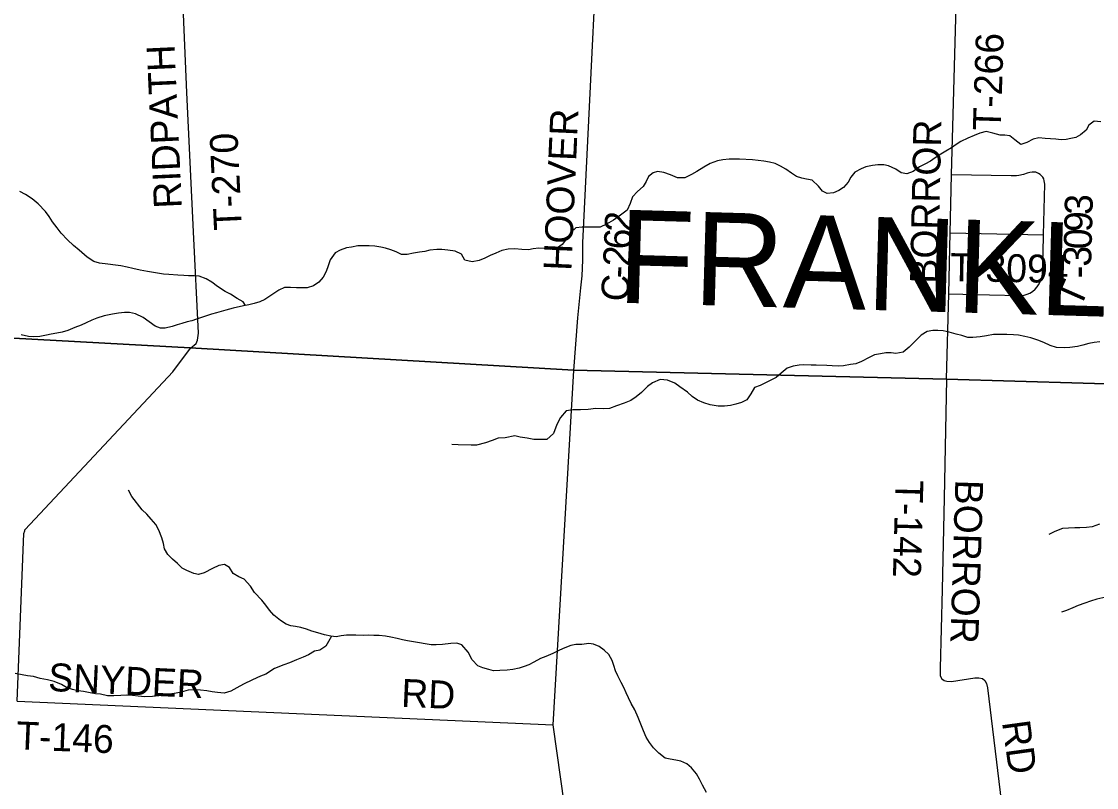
# Model space of a CAD drawing. Extents: x 114843 to 284848, y 317643 to 566895.
# Drawn here: x 179255 to 190810, y 325529 to 333758 of the extents above; entities that cross this region are included whole.
import ezdxf

# ---------------------------------------------------------------- set-up
doc = ezdxf.new("R2010")
doc.units = 0
for name, color, linetype in [('GM_X_County', 7, 'Continuous'), ('GM_X_County_Road', 7, 'Continuous'), ('GM_X_County_Road_Text', 7, 'Continuous'), ('GM_X_County_Text', 7, 'Continuous'), ('GM_X_Minor_River', 7, 'Continuous'), ('GM_X_Township', 7, 'Continuous'), ('GM_X_Township_Road', 7, 'Continuous'), ('GM_X_Township_Road_Text', 7, 'Continuous')]:
    doc.layers.add(name, color=color, linetype=linetype)

msp = doc.modelspace()

# ---------------------------------------------------------------- linework, layer by layer
at = {"layer": 'GM_X_County'}
for points in [[(234342, 327551), (226718, 328004), (223790, 328228), (218560, 328476), (218545, 328480), (213225, 328765), (208151, 329070), (208095, 329072), (206187, 329142), (202770, 329336), (202310, 329362), (198524, 329604), (197724, 329650), (193708, 329789), (193408, 329799), (192869, 329809), (189197, 329917), (185190, 330012), (181070, 330253), (177726, 330436)], [(177726, 330436), (181070, 330253), (185190, 330012), (189197, 329917), (192869, 329809), (193408, 329799), (193708, 329789), (197724, 329650), (198524, 329604), (202310, 329362), (202770, 329336), (206187, 329142), (208095, 329072), (208151, 329070), (213225, 328765), (218545, 328480), (218560, 328476), (223790, 328228), (226718, 328004), (234342, 327551)]]:
    msp.add_lwpolyline(points, dxfattribs=at)
at = {"layer": 'GM_X_County_Road'}
for points in [[(185191, 330009), (185235, 330573), (185269, 330895), (185281, 331026), (185287, 331193), (185289, 331381), (185389, 333425), (185415, 333935), (185439, 334426), (185464, 334887), (185471, 335221), (185475, 335891), (185479, 336859), (185483, 337354)], [(185504, 322567), (185296, 323893), (184971, 326203), (185191, 330009)]]:
    msp.add_lwpolyline(points, dxfattribs=at)
at = {"layer": 'GM_X_Minor_River'}
for points in [[(190858, 332681), (190786, 332687), (190729, 332643), (190697, 332591), (190639, 332541), (190587, 332513), (190533, 332501), (190483, 332491), (190431, 332487), (190371, 332493), (190315, 332496), (190259, 332502), (190191, 332508), (190129, 332494), (190061, 332458), (189997, 332436), (189933, 332486), (189877, 332528), (189825, 332536), (189773, 332538), (189697, 332557), (189625, 332575), (189557, 332559), (189496, 332533), (189428, 332505), (189352, 332467), (189300, 332435), (189250, 332401), (189190, 332365), (189136, 332331)], [(189136, 332331), (189076, 332295), (189026, 332257), (188964, 332227), (188906, 332195), (188841, 332147), (188773, 332121), (188711, 332131), (188653, 332173), (188575, 332209), (188523, 332217), (188459, 332217), (188401, 332212), (188331, 332196), (188279, 332176), (188213, 332138), (188171, 332086), (188139, 332031), (188091, 331973), (188040, 331943), (187984, 331919), (187916, 331911), (187864, 331936), (187822, 331988), (187752, 332052), (187694, 332064), (187642, 332074), (187586, 332094), (187530, 332127), (187470, 332171), (187412, 332205), (187356, 332231), (187294, 332247), (187234, 332259), (187172, 332265), (187112, 332271), (186972, 332280), (186922, 332280), (186860, 332280), (186794, 332272), (186736, 332262), (186658, 332234), (186588, 332192), (186514, 332148), (186456, 332116), (186384, 332080), (186305, 332078), (186230, 332110), (186161, 332136), (186093, 332145), (186043, 332131), (185993, 332093), (185969, 332040), (185937, 331986), (185875, 331932), (185823, 331876), (185799, 331804), (185767, 331732), (185692, 331678), (185620, 331624), (185544, 331580), (185474, 331550), (185416, 331548), (185354, 331548), (185280, 331550), (185214, 331540), (185164, 331494), (185124, 331438), (185067, 331364), (185005, 331320), (184937, 331308), (184873, 331320), (184815, 331324), (184755, 331316), (184705, 331304), (184633, 331309), (184557, 331315), (184485, 331311), (184419, 331297), (184353, 331269), (184293, 331243), (184235, 331217), (184173, 331191), (184099, 331177), (184020, 331195), (183985, 331259), (183915, 331290), (183839, 331300), (183773, 331310), (183720, 331310), (183644, 331300), (183592, 331288), (183534, 331280), (183468, 331270), (183400, 331256), (183340, 331256), (183282, 331282), (183226, 331304), (183168, 331323), (183116, 331333), (183054, 331343)], [(181663, 330708), (181638, 330745), (181572, 330783), (181500, 330830), (181444, 330858), (181362, 330910), (181302, 330956), (181240, 330994), (181166, 331021), (181112, 331027), (181050, 331027), (181000, 331029), (180936, 331033), (180838, 331041), (180780, 331043), (180696, 331057), (180608, 331073), (180532, 331088), (180452, 331106), (180392, 331120), (180322, 331134), (180266, 331140), (180182, 331150), (180092, 331162), (180032, 331178), (179962, 331227), (179874, 331303), (179814, 331353), (179748, 331413), (179680, 331484), (179638, 331542), (179590, 331606), (179552, 331664), (179512, 331718), (179436, 331799), (179370, 331853), (179300, 331901), (179236, 331933)], [(183054, 331343), (182992, 331349), (182926, 331349), (182872, 331347), (182802, 331335), (182748, 331325), (182682, 331303), (182626, 331271), (182573, 331197), (182553, 331133), (182529, 331071), (182497, 331011), (182451, 330957), (182395, 330917), (182325, 330897), (182273, 330895), (182211, 330897), (182147, 330901), (182083, 330899), (182021, 330871), (181870, 330771), (181818, 330747), (181756, 330729), (181700, 330715), (181640, 330703), (181532, 330679), (181452, 330657), (181352, 330629), (181298, 330615), (181190, 330577), (181137, 330559), (181085, 330544), (181035, 330530), (180979, 330512), (180927, 330498), (180875, 330482), (180799, 330464), (180749, 330464), (180693, 330486), (180627, 330532), (180563, 330578), (180479, 330619), (180415, 330633), (180361, 330631), (180297, 330625), (180233, 330615), (180143, 330595), (180065, 330571), (180011, 330549), (179949, 330521), (179898, 330497), (179828, 330469), (179754, 330439), (179694, 330421), (179636, 330409), (179576, 330399), (179524, 330387), (179454, 330375), (179388, 330369), (179332, 330373), (179252, 330392)], [(190844, 330318), (190784, 330308), (190728, 330298), (190664, 330280), (190604, 330268), (190522, 330254), (190464, 330252), (190381, 330254), (190313, 330278), (190245, 330309), (190181, 330335), (190103, 330359), (190041, 330375), (189973, 330387), (189917, 330391), (189845, 330395), (189703, 330395), (189627, 330382), (189559, 330370), (189479, 330362), (189427, 330364), (189363, 330386), (189303, 330398), (189225, 330422), (189161, 330434), (189103, 330440), (189051, 330440), (188989, 330427), (188925, 330387), (188856, 330320), (188798, 330260), (188732, 330206), (188654, 330190), (188602, 330197), (188546, 330197), (188488, 330189), (188424, 330177), (188368, 330147), (188284, 330105), (188224, 330081), (188166, 330073), (188092, 330057), (188033, 330055), (187969, 330057), (187911, 330061), (187795, 330065), (187743, 330067), (187665, 330068), (187615, 330066), (187549, 330054), (187485, 330032), (187419, 329980), (187365, 329933)], [(187365, 329932), (187196, 329848), (187133, 329825), (187094, 329758), (187051, 329693), (186993, 329664), (186934, 329647), (186876, 329634), (186810, 329625), (186744, 329626), (186658, 329639), (186590, 329662), (186521, 329690), (186465, 329730), (186412, 329777), (186331, 329832), (186276, 329871), (186200, 329904), (186120, 329912), (186036, 329875), (185985, 329836), (185920, 329773), (185863, 329724), (185804, 329688), (185734, 329657), (185651, 329630), (185577, 329600), (185509, 329597), (185427, 329600), (185347, 329589), (185265, 329585), (185180, 329586), (185110, 329577), (185047, 329505), (185010, 329430), (184974, 329332), (184903, 329268), (184761, 329266), (184691, 329283), (184615, 329293), (184558, 329306), (184455, 329287), (184377, 329281), (184315, 329258), (184242, 329231), (184146, 329205), (184088, 329208), (183948, 329210), (183882, 329213)], [(185603, 326893), (185568, 326959), (185518, 327006), (185463, 327043), (185403, 327070), (185353, 327077), (185279, 327066), (185215, 327065), (185159, 327056), (185095, 327031), (185038, 327004), (184965, 326967), (184891, 326935), (184835, 326914), (184762, 326877), (184709, 326848), (184657, 326827), (184605, 326810), (184538, 326795), (184474, 326788), (184396, 326785), (184328, 326783), (184278, 326795), (184215, 326814), (184161, 326835), (184098, 326902), (184057, 326983), (183989, 327063), (183935, 327080), (183871, 327077), (183779, 327065), (183712, 327060), (183660, 327063), (183593, 327074), (183533, 327083), (183467, 327094), (183405, 327105), (183349, 327116), (183293, 327131), (183226, 327144), (183166, 327155), (183100, 327160), (183042, 327163), (182990, 327164), (182926, 327163), (182848, 327164), (182748, 327164), (182692, 327157), (182639, 327148), (182579, 327153), (182512, 327168), (182440, 327189), (182376, 327210), (182319, 327231), (182257, 327248), (182201, 327257), (182151, 327264), (182099, 327285), (182040, 327323), (181969, 327380), (181922, 327433), (181881, 327488), (181837, 327542), (181759, 327625), (181718, 327690), (181647, 327767), (181593, 327792), (181530, 327829), (181491, 327891), (181438, 327926), (181377, 327915), (181307, 327882), (181218, 327836), (181158, 327817), (181108, 327828), (181034, 327861), (180983, 327884), (180933, 327934), (180880, 327983), (180829, 328032), (180792, 328094), (180783, 328150), (180764, 328210), (180733, 328295), (180698, 328353), (180649, 328412), (180602, 328464), (180551, 328513), (180441, 328655), (180404, 328723)], [(190843, 328357), (190765, 328330), (190704, 328323), (190632, 328317), (190576, 328318), (190510, 328315), (190446, 328310), (190362, 328279), (190297, 328246)], [(191590, 327427), (191540, 327436), (191487, 327467), (191422, 327530), (191348, 327549), (191292, 327572), (191227, 327585), (191133, 327588), (191069, 327585), (191008, 327581), (190952, 327579), (190878, 327567), (190812, 327552), (190745, 327531), (190683, 327508), (190611, 327483), (190554, 327458), (190488, 327432), (190433, 327411)], [(182586, 327153), (182556, 327097), (182526, 327046), (182463, 327003), (182405, 326992), (182340, 326953), (182282, 326928), (182211, 326902), (182135, 326867), (182074, 326848), (181973, 326806), (181882, 326748), (181824, 326725), (181739, 326686), (181643, 326638), (181570, 326599), (181507, 326565), (181435, 326544), (181361, 326551), (181305, 326558), (181249, 326567), (181181, 326574), (181129, 326579), (181045, 326574), (180971, 326552), (180919, 326542), (180848, 326532), (180788, 326521), (180730, 326514), (180662, 326507), (180580, 326504), (180508, 326509), (180448, 326516), (180380, 326520), (180324, 326517), (180248, 326514), (180178, 326513), (180106, 326530), (180052, 326535), (179994, 326546), (179922, 326559), (179863, 326568), (179803, 326581), (179739, 326602), (179684, 326635), (179606, 326668), (179534, 326685), (179455, 326699), (179383, 326720), (179319, 326729), (179261, 326738), (179189, 326755)], [(186618, 325476), (186575, 325554), (186542, 325619), (186509, 325675), (186458, 325740), (186407, 325784), (186341, 325813), (186287, 325822), (186227, 325833), (186174, 325844), (186104, 325897), (186047, 325956), (186006, 326011), (185969, 326071), (185942, 326137), (185912, 326208), (185885, 326282), (185846, 326364), (185807, 326433), (185780, 326491), (185753, 326545), (185728, 326602), (185699, 326658), (185666, 326728), (185641, 326781), (185622, 326841), (185603, 326893)]]:
    msp.add_lwpolyline(points, dxfattribs=at)
at = {"layer": 'GM_X_Township'}
for points in [[(177726, 330436), (181070, 330253), (185190, 330012), (189197, 329917), (192869, 329809), (193408, 329799), (193708, 329789), (197724, 329650), (198524, 329604), (202310, 329362)], [(202310, 329362), (198524, 329604), (197724, 329650), (193708, 329789), (193408, 329799), (192869, 329809), (189197, 329917), (185190, 330012), (181070, 330253), (177726, 330436)]]:
    msp.add_lwpolyline(points, dxfattribs=at)
at = {"layer": 'GM_X_Township_Road'}
for p, q in [((189237, 331488), (190241, 331467)), ((191454, 329848), (189199, 329914)), ((179210, 326456), (184971, 326203))]:
    msp.add_line(p, q, dxfattribs=at)
for points in [[(189199, 329914), (189222, 330833), (189237, 331488), (189252, 332112), (189406, 337676), (189404, 338099), (189443, 339319), (189460, 339877), (189447, 339954)], [(181072, 330250), (181133, 330298), (181148, 330336), (181158, 330410), (181103, 331497), (181034, 332995), (180969, 334515), (180934, 335955), (180905, 336831), (180914, 337033), (180948, 337573)], [(189222, 330833), (189373, 330830), (189658, 330823), (189986, 330815), (190006, 330816), (190032, 330819), (190063, 330828), (190092, 330841), (190122, 330859), (190150, 330883), (190171, 330906), (190187, 330929), (190201, 330954), (190215, 330987), (190225, 331022), (190230, 331051), (190233, 331182), (190236, 331276), (190241, 331467), (190253, 332012), (190249, 332048), (190242, 332067), (190232, 332085), (190220, 332100), (190205, 332114), (190188, 332126), (190173, 332133), (190158, 332138), (190141, 332140), (190117, 332140), (190092, 332136), (190063, 332128), (190024, 332116), (189974, 332105), (189949, 332101), (189924, 332101), (189893, 332099), (189252, 332112)], [(179296, 328300), (180881, 329993), (181072, 330250)], [(189199, 329914), (189174, 328636), (189152, 327657), (189128, 326810), (189130, 326730), (189147, 326697), (189173, 326678), (189202, 326672), (189252, 326669), (189502, 326707), (189546, 326708), (189585, 326699), (189610, 326679), (189628, 326647), (189639, 326599), (189897, 324469)], [(179210, 326456), (179282, 328258), (179290, 328287), (179292, 328296), (179296, 328300)]]:
    msp.add_lwpolyline(points, dxfattribs=at)

# ---------------------------------------------------------------- texts
at = {"layer": 'GM_X_County_Road_Text'}
for s, rotation, p in [('HOOVER', 87.4786, (185165, 331076)), ('2', 87.5056, (185821, 331490)), ('6', 87.4509, (185813, 331305)), ('2', 87.21, (185804, 331119)), ('-', 86.8706, (185797, 330994)), ('C', 85.7632, (185779, 330742))]:
    msp.add_text(s, height=300, rotation=rotation, dxfattribs=at).set_placement(p)
at = {"layer": 'GM_X_County_Text'}
msp.add_text('FRANKLIN COUNTY', height=1000.08, rotation=358.3511, dxfattribs=at).set_placement((185655, 330738))
at = {"layer": 'GM_X_Township_Road_Text'}
for s, rotation, p in [('T-266', 88.1674, (189780, 332583)), ('RIDPATH', 92.633, (180980, 331756)), ('BORROR', 88.7525, (189105, 330940)), ('T-270', 92.6485, (181625, 331522)), ('3', 88.5668, (190766, 331677)), ('9', 88.56, (190762, 331493)), ('0', 88.5164, (190757, 331308)), ('T-3094', 359.0099, (189236, 330970)), ('3', 88.3466, (190751, 331122)), ('-', 89.7222, (190751, 331000)), ('T', 66.229, (190633, 330665)), ('T-142', 268.4477, (188650, 328834)), ('BORROR', 268.2423, (189293, 328839)), ('SNYDER', 357.3184, (179538, 326567)), ('RD', 357.4517, (183332, 326397)), ('T-146', 357.6068, (179194, 325940)), ('RD', 277.844, (189794, 326231))]:
    msp.add_text(s, height=300, rotation=rotation, dxfattribs=at).set_placement(p)

doc.saveas('drawing.dxf')
